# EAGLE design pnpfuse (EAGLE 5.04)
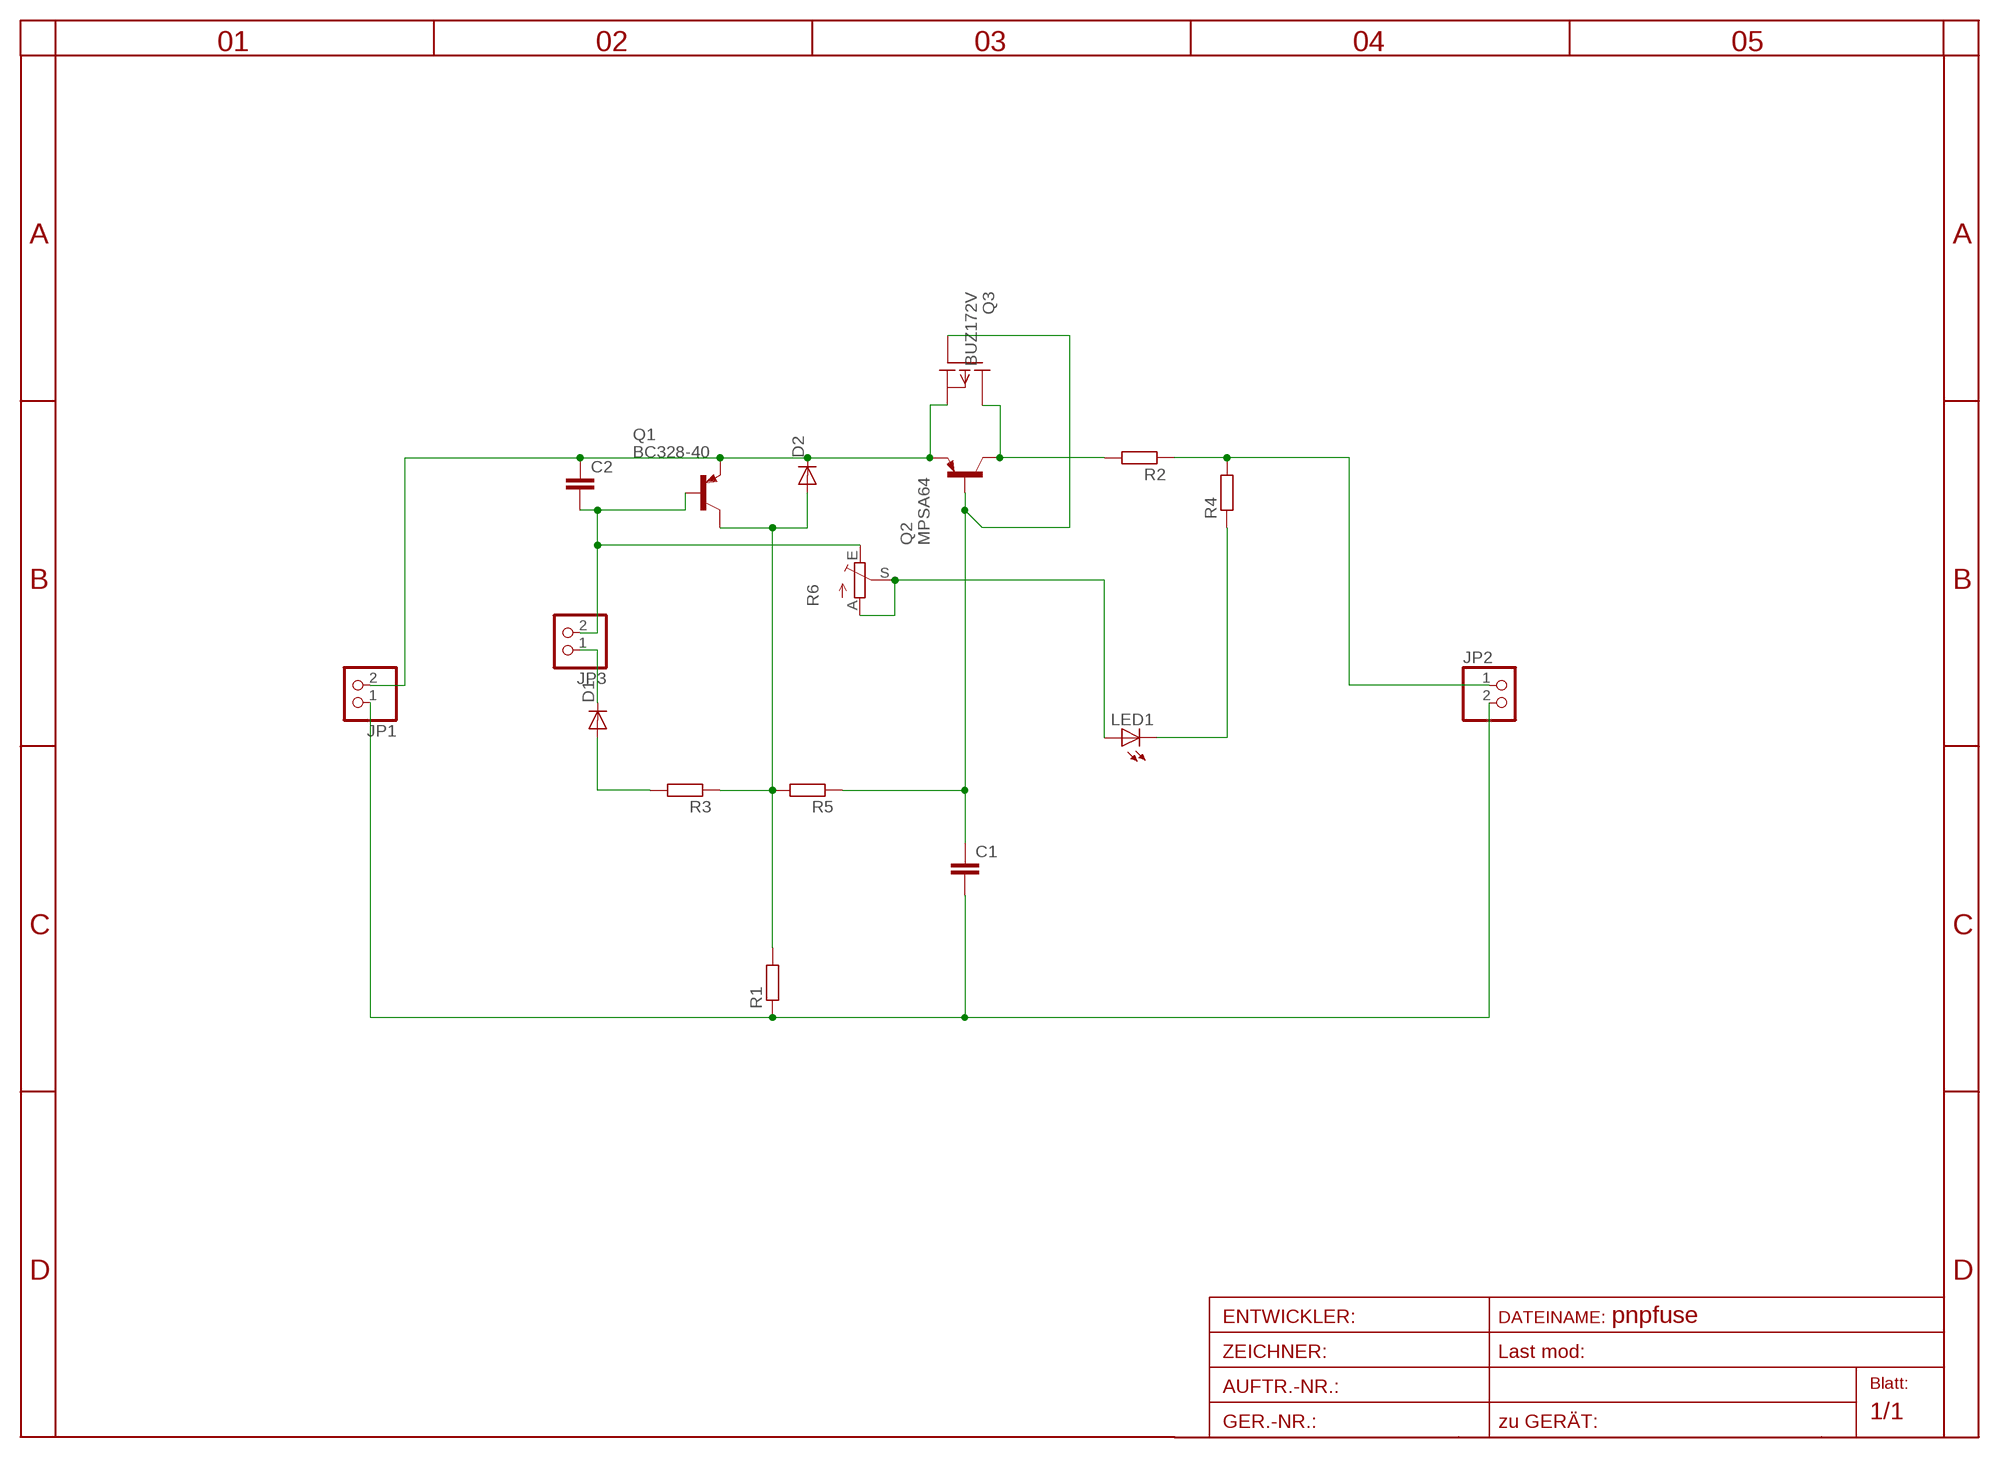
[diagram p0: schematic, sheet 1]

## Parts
C1  C-EU025-040X050  [C025-040X050]
C2  C-EU025-024X044  [C025-024X044]
D1  DIODE-D-7.5  [D-7.5]
D2  DIODE-D-5  [D-5]
JP1  PINHD-1X2  [1X02]
JP2  PINHD-1X2  [1X02]
JP3  PINHD-1X2  [1X02]
LED1  LED3MM  [LED3MM]
Q1  BC328-40  [TO92-EBC]
Q2  MPSA64  [TO92-CBE]
Q3  BUZ172V  [TO220V]
R1  R-EU_0204/7  [0204/7]
R2  R-EU_0204/5  [0204/5]
R3  R-EU_0204/7  [0204/7]
R4  R-EU_0207/12  [0207/12]
R5  R-EU_0204/5  [0204/5]
R6  TRIM_EU-CA6V  [CA6V]

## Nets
N$1: C1.2 JP1.1 JP2.2 R1.1
N$2: C2.1 D2.C JP1.2 Q1.E Q2.E Q3.3(S)
N$3: LED1.A R6.A R6.S
N$4: D2.A Q1.C R1.2 R3.1 R5.2
N$5: D1.A R3.2
N$6: D1.C JP3.1
N$7: C1.1 Q2.B Q3.1(G) R5.1
N$8: JP2.1 R2.1 R4.2
N$9: Q2.C Q3.2(D) R2.2
N$11: LED1.K(C) R4.1
N$12: C2.2 JP3.2 Q1.B R6.E

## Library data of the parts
C1 C2 = rcl-2:C-EU: CAPACITOR, European symbol
D1 D2 = diode-1:DIODE-: DIODE
JP1-JP3 = pinhead:PINHD-1X2: PIN HEADER
LED1 = led:LED: LED
Q1 = transistor-pnp:BC328*: PNP Transistror
Q2 = transistor-pnp:MPSA64*: PNP Transistror
Q3 = transistor-fet:BUZ172: P-Channel Enhancement MOSFET -100V; -5A; 0,8Ohm
R1-R5 = rcl-2:R-EU_: RESISTOR, European symbol
R6 = pot:TRIM_EU-: POTENTIOMETER

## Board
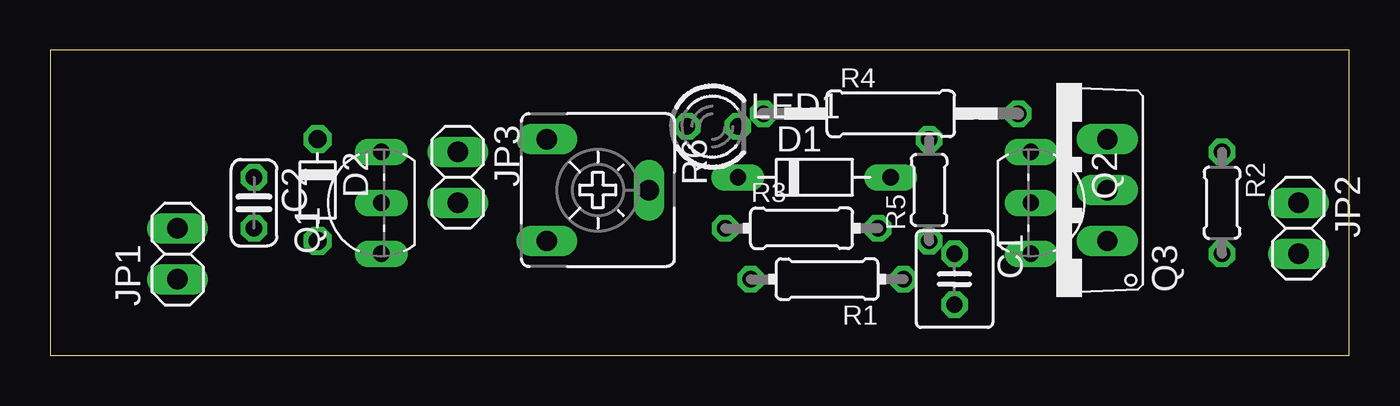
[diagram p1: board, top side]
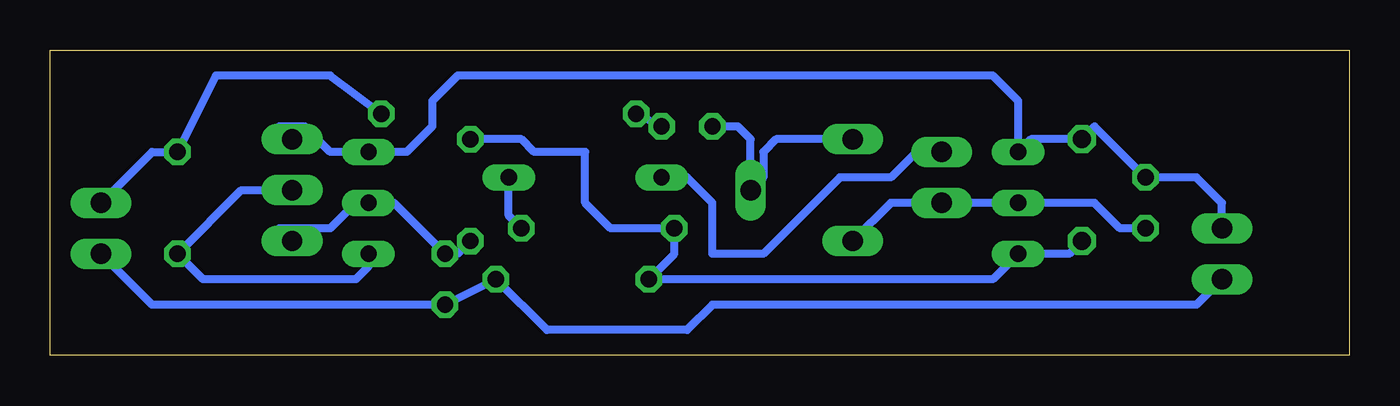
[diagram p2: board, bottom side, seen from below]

Size 64.77 x 15.24 mm. Coordinates in mm from the lower left corner, seen from the top.
Outline: 0,0 64.77,0 64.77,15.24 0,15.24 0,0
Copper layers (1*16): Top 0.035mm / dielectric 1.5mm / Bottom 0.035mm
Design rules "default": minimum track width 10mil, minimum drill 24mil, track to track 8mil, track to pad 8mil, pad to pad 8mil, via to via 8mil, smd to smd 8mil, copper to edge 40mil, drill to drill 8mil, minimum pad ring 10mil, minimum via ring 8mil, stop-mask expansion 4mil, vias tented up to drill 0mil, thermal gap 10mil

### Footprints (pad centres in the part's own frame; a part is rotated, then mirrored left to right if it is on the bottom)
C025-040X050 = drill 0.813 octagon: 1 -1.27,0; 2 1.27,0
C025-024X044 = drill 0.813 octagon: 1 -1.27,0; 2 1.27,0
D-7.5 = drill 0.813 long: A 3.81,0; C -3.81,0
D-5 = drill 0.9 octagon: A 2.54,0; C -2.54,0
1X02 = drill 1.016 long: 1 -1.27,0; 2 1.27,0
LED3MM = drill 0.813 octagon: A -1.27,0; K 1.27,0
TO92-EBC = drill 0.813 long: B 0,-1.27; C -2.54,-1.27; E 2.54,-1.27
TO92-CBE = drill 0.813 long: B 0,0; C 2.54,0; E -2.54,0
TO220V = drill 1.016 long: 1 -2.54,-2.54; 2 0,-2.54; 3 2.54,-2.54
0204/7 = drill 0.813 octagon: 1 -3.81,0; 2 3.81,0
0204/5 = drill 0.813 octagon: 1 -2.54,0; 2 2.54,0
0207/12 = drill 0.813 octagon: 1 -6.35,0; 2 6.35,0
CA6V = drill 1.016 long: A -2.54,-2.54; E 2.54,-2.54; S 0,2.54

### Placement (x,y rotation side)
C1  45.09,3.81 270 top
C2  10.16,7.62 270 top
D1  38.1,8.89 0 top
D2  13.34,8.26 270 top
JP1  6.35,5.08 90 top
JP2  62.23,6.35 270 top
JP3  20.32,8.89 270 top
LED1  33.02,11.43 0 top
Q1  15.24,7.62 90 top
Q2  48.9,7.62 270 top
Q3  50.16,8.26 90 top
R1  38.73,3.81 180 top
R2  58.42,7.62 270 top
R3  37.47,6.35 0 top
R4  41.91,12.06 0 top
R5  43.81,8.26 90 top
R6  27.3,8.26 270 top

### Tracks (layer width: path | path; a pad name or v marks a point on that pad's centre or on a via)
N$1
  Bottom 0.406: JP1.1 7.62,2.54 31.75,2.54 33.02,1.27 40.01,1.27 R1.1 C1.2 59.69,2.54 JP2.2
N$2
  Bottom 0.406: JP1.2 6.35,7.62 7.62,8.89 C2.1 12.7,11.43 D2.C 15.88,10.79 Q1.E 16.51,12.7 17.78,13.97 44.45,13.97 45.72,12.7 45.72,11.43 46.99,10.16 Q2.E 50.8,10.16 52.07,11.43 53.34,11.43 Q3.3
N$3
  Bottom 0.406: R6.A 28.57,10.79 29.21,10.16 29.21,8.89 R6.S 29.84,10.79 30.48,11.43 LED1.A
N$4
  Bottom 0.406: D2.A 13.97,5.08 Q1.C 17.78,3.81 R1.2 33.66,5.08 R3.1 36.83,6.35 38.1,7.62 38.1,10.16 40.64,10.16 41.27,10.79 R5.2
N$5
  Bottom 0.406: D1.A 41.91,6.99 R3.2
N$6
  Bottom 0.406: JP3.1 21.59,10.16 22.86,8.89 25.4,8.89 29.21,5.08 31.75,5.08 31.75,7.62 33.02,8.89 D1.C
N$7
  Bottom 0.406: Q3.1 53.34,6.35 50.8,6.35 49.53,7.62 Q2.B 47.62,7.62 C1.1 44.45,5.08 R5.1
N$8
  Bottom 0.406: R4.2 50.8,13.97 56.52,13.97 R2.1 59.69,10.16 JP2.1
N$9
  Bottom 0.406: Q3.2 55.24,8.26 R2.2 57.15,3.81 49.53,3.81 48.9,4.45 Q2.C
N$11
  Bottom 0.406: LED1.K R4.1
N$12
  Bottom 0.406: C2.2 11.43,6.35 12.7,7.62 Q1.B JP3.2 22.86,7.62 R6.E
